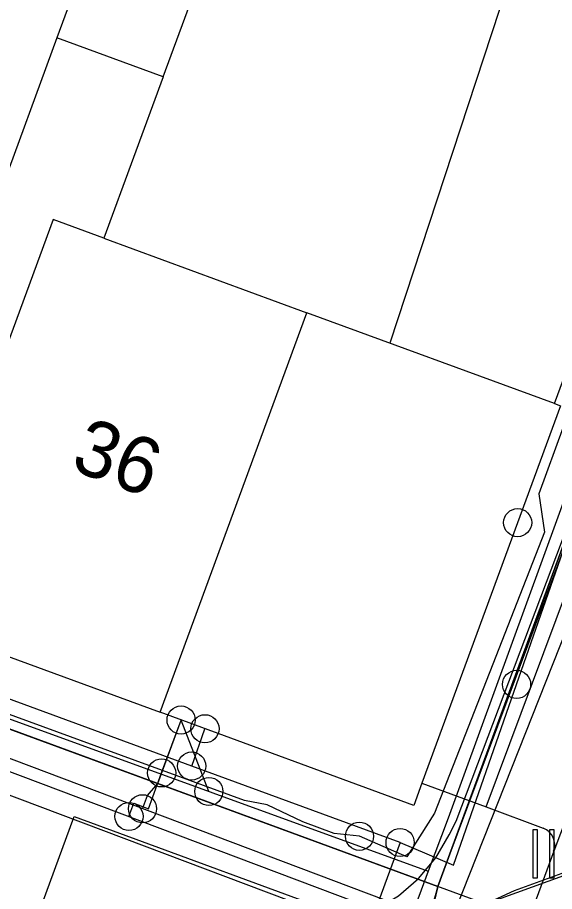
# Model space of a CAD drawing. Extents: x 192672 to 192910, y 446344 to 446512.
# Drawn here: x 192731.6 to 192741.13, y 446406.75 to 446422.27 of the extents above; entities that cross this region are included whole.
import ezdxf

# ---------------------------------------------------------------- set-up
doc = ezdxf.new("R2010")
doc.units = 0
for name, color, linetype in [('B-OI-KL-()_PUNTVANLEVERING_WATER-S', 7, 'Continuous'), ('B-OI-KL-BUISLEIDING_OLIEGASCHEMICALIEN_GASLAGEDRUK-G', 7, 'Continuous'), ('B-OI-KL-DATA-G', 7, 'Continuous'), ('B-OI-KL-DATA_GTWP-S', 7, 'Continuous'), ('B-OI-KL-DATA_HANDHOLE-S', 7, 'Continuous'), ('B-OI-KL-DATA_KABELBED-G', 7, 'Continuous'), ('B-OI-KL-DATA_MOF-S', 7, 'Continuous'), ('B-OI-KL-ET_LS-G', 7, 'Continuous'), ('B-OI-KL-ET_LS_DELIVERYPOINT-S', 7, 'Continuous'), ('B-OI-KL-ET_LS_MOF-S', 7, 'Continuous'), ('B-OI-KL-ET_MS-G', 7, 'Continuous'), ('B-OI-KL-ET_MS_MANTELBUIS-G', 7, 'Continuous'), ('B-OI-KL-GAS_LD_AFTAKZADEL-S', 7, 'Continuous'), ('B-OI-KL-GAS_LD_DELIVERYPOINT-S', 7, 'Continuous'), ('B-OI-KL-WATER-G', 7, 'Continuous'), ('Default', 7, 'Continuous'), ('huisnummerreeks BGT', 7, 'Continuous'), ('kant open verharding', 7, 'Continuous'), ('kant verharding', 7, 'Continuous'), ('kolk', 7, 'Continuous'), ('pand op maaiveld vlak', 7, 'Continuous'), ('verkeerseiland - berm', 7, 'Continuous')]:
    doc.layers.add(name, color=color, linetype=linetype)

# ---------------------------------------------------------------- blocks, each defined once
blk = doc.blocks.new('B-OI-KL-GAS_LD_AFTAKZADEL-S')
at = {"layer": 'Default'}
blk.add_circle((0, 0), 0.25, dxfattribs=at)
blk = doc.blocks.new('B-OI-KL-GAS_LD_DELIVERYPOINT-S')
at = {"layer": 'Default'}
blk.add_circle((0, 0), 0.25, dxfattribs=at)
blk = doc.blocks.new('B-OI-KL-ET_LS_DELIVERYPOINT-S')
at = {"layer": 'Default'}
blk.add_circle((0, 0), 0.25, dxfattribs=at)
blk = doc.blocks.new('B-OI-KL-ET_LS_MOF-S')
at = {"layer": 'Default'}
blk.add_circle((0, 0), 0.25, dxfattribs=at)
blk = doc.blocks.new('B-OI-KL-DATA_HANDHOLE-S')
at = {"layer": 'Default'}
blk.add_circle((0, 0), 0.25, dxfattribs=at)
blk = doc.blocks.new('B-OI-KL-()_PUNTVANLEVERING_WATER-S')
at = {"layer": 'Default'}
blk.add_circle((0, 0), 0.25, dxfattribs=at)
blk = doc.blocks.new('B-OI-KL-DATA_GTWP-S')
at = {"layer": 'Default'}
blk.add_circle((0, 0), 0.25, dxfattribs=at)
blk = doc.blocks.new('B-OI-KL-DATA_MOF-S')
at = {"layer": 'Default'}
blk.add_circle((0, 0), 0.25, dxfattribs=at)

msp = doc.modelspace()

# ---------------------------------------------------------------- linework, layer by layer
at = {"layer": 'B-OI-KL-BUISLEIDING_OLIEGASCHEMICALIEN_GASLAGEDRUK-G'}
for points in [[(192739.245, 446406.116), (192738.416, 446406.482), (192717.09, 446414.534), (192687.866, 446425.386), (192686.502, 446425.892), (192685.933, 446426.1), (192675.743, 446429.821)], [(192742.217, 446413.618), (192739.245, 446406.116)], [(192733.815, 446408.219), (192733.903, 446408.453), (192734.086, 446408.668), (192734.5, 446409.795)]]:
    msp.add_lwpolyline(points, dxfattribs=at)
at = {"layer": 'B-OI-KL-DATA-G'}
for points in [[(192768.74, 446486.807), (192749.794, 446435.599), (192742.072, 446415.039), (192739.06, 446406.841), (192720.2, 446413.77), (192719.012, 446414.118), (192696.077, 446422.823), (192683.193, 446427.673), (192678.122, 446429.261), (192675.743, 446430.156)], [(192768.74, 446486.807), (192749.794, 446435.599), (192742.072, 446415.039), (192739.06, 446406.841), (192738.917, 446406.249), (192738.75, 446405.758), (192738.438, 446405.088), (192738.002, 446404.406), (192737.543, 446403.858), (192737.067, 446403.408), (192736.56, 446403.025), (192736.06, 446402.723), (192733.684, 446396.245), (192734.518, 446394.712), (192730.316, 446383.423), (192727.316, 446375.697), (192722.899, 446364.033), (192722.458, 446362.715), (192718.077, 446351.086), (192716.68, 446347.404), (192715.968, 446345.556)], [(192768.74, 446486.807), (192749.794, 446435.599), (192742.072, 446415.039), (192739.06, 446406.841), (192738.917, 446406.249), (192738.75, 446405.758), (192738.438, 446405.088), (192738.002, 446404.406), (192737.543, 446403.858), (192737.067, 446403.408), (192736.56, 446403.025), (192736.06, 446402.723), (192733.684, 446396.245), (192734.518, 446394.712), (192730.316, 446383.423), (192727.316, 446375.697), (192722.899, 446364.033), (192722.458, 446362.715), (192718.077, 446351.086), (192716.68, 446347.404), (192715.968, 446345.556)], [(192768.74, 446486.807), (192749.794, 446435.599), (192742.072, 446415.039), (192739.06, 446406.841), (192738.917, 446406.249), (192738.75, 446405.758), (192738.438, 446405.088), (192738.002, 446404.406), (192737.543, 446403.858), (192737.067, 446403.408), (192736.56, 446403.025), (192736.06, 446402.723), (192733.684, 446396.245), (192734.518, 446394.712), (192730.316, 446383.423), (192727.316, 446375.697), (192722.899, 446364.033), (192722.458, 446362.715), (192718.077, 446351.086), (192716.68, 446347.404), (192715.968, 446345.556)], [(192768.74, 446486.807), (192749.794, 446435.599), (192742.072, 446415.039), (192739.06, 446406.841), (192738.917, 446406.249), (192738.75, 446405.758), (192738.438, 446405.088), (192738.002, 446404.406), (192737.543, 446403.858), (192737.067, 446403.408), (192736.56, 446403.025), (192736.06, 446402.723), (192733.684, 446396.245), (192734.518, 446394.712), (192730.316, 446383.423), (192727.316, 446375.697), (192722.899, 446364.033), (192722.458, 446362.715), (192718.077, 446351.086), (192716.68, 446347.404), (192715.968, 446345.556)], [(192768.74, 446486.807), (192749.794, 446435.599), (192742.072, 446415.039), (192739.06, 446406.841), (192738.917, 446406.249), (192738.75, 446405.758), (192738.438, 446405.088), (192738.002, 446404.406), (192737.543, 446403.858), (192737.067, 446403.408), (192736.56, 446403.025), (192736.06, 446402.723), (192733.684, 446396.245), (192734.518, 446394.712), (192730.316, 446383.423), (192727.316, 446375.697), (192722.899, 446364.033), (192722.458, 446362.715), (192718.077, 446351.086), (192716.68, 446347.404), (192715.968, 446345.556)], [(192768.74, 446486.807), (192749.794, 446435.599), (192742.072, 446415.039), (192739.06, 446406.841), (192738.917, 446406.249), (192738.75, 446405.758), (192738.438, 446405.088), (192738.002, 446404.406), (192737.543, 446403.858), (192737.067, 446403.408), (192736.56, 446403.025), (192736.06, 446402.723), (192733.684, 446396.245), (192734.518, 446394.712), (192730.316, 446383.423), (192727.316, 446375.697), (192722.899, 446364.033), (192722.458, 446362.715), (192718.077, 446351.086), (192716.68, 446347.404), (192715.968, 446345.556)], [(192768.74, 446486.807), (192749.794, 446435.599), (192742.072, 446415.039), (192739.06, 446406.841), (192738.917, 446406.249), (192738.75, 446405.758), (192738.438, 446405.088), (192738.002, 446404.406), (192737.543, 446403.858), (192737.067, 446403.408), (192736.56, 446403.025), (192736.06, 446402.723), (192733.684, 446396.245), (192734.518, 446394.712), (192730.316, 446383.423), (192727.316, 446375.697), (192722.899, 446364.033), (192722.458, 446362.715), (192718.077, 446351.086), (192716.68, 446347.404), (192715.968, 446345.556)], [(192768.74, 446486.807), (192749.794, 446435.599), (192742.072, 446415.039), (192739.06, 446406.841), (192738.917, 446406.249), (192738.75, 446405.758), (192738.438, 446405.088), (192738.002, 446404.406), (192737.543, 446403.858), (192737.067, 446403.408), (192736.56, 446403.025), (192736.06, 446402.723), (192733.684, 446396.245), (192734.518, 446394.712), (192730.316, 446383.423), (192727.316, 446375.697), (192722.899, 446364.033), (192722.458, 446362.715), (192718.077, 446351.086), (192716.68, 446347.404), (192715.968, 446345.556)], [(192768.74, 446486.807), (192749.794, 446435.599), (192742.072, 446415.039), (192739.06, 446406.841), (192738.917, 446406.249), (192738.75, 446405.758), (192738.438, 446405.088), (192738.002, 446404.406), (192737.543, 446403.858), (192737.067, 446403.408), (192736.56, 446403.025), (192736.06, 446402.723), (192733.684, 446396.245), (192734.518, 446394.712), (192730.316, 446383.423), (192727.316, 446375.697), (192722.899, 446364.033), (192722.458, 446362.715), (192718.077, 446351.086), (192716.68, 446347.404), (192715.968, 446345.556)], [(192768.74, 446486.807), (192749.794, 446435.599), (192742.072, 446415.039), (192739.06, 446406.841), (192738.917, 446406.249), (192738.75, 446405.758), (192738.438, 446405.088), (192738.002, 446404.406), (192737.543, 446403.858), (192737.067, 446403.408), (192736.56, 446403.025), (192736.06, 446402.723), (192733.684, 446396.245), (192734.518, 446394.712), (192730.316, 446383.423), (192727.316, 446375.697), (192722.899, 446364.033), (192722.458, 446362.715), (192718.077, 446351.086), (192716.68, 446347.404), (192715.968, 446345.556)], [(192768.74, 446486.807), (192749.794, 446435.599), (192742.072, 446415.039), (192739.06, 446406.841), (192738.917, 446406.249), (192738.75, 446405.758), (192738.438, 446405.088), (192738.002, 446404.406), (192737.543, 446403.858), (192737.067, 446403.408), (192736.56, 446403.025), (192736.06, 446402.723), (192733.684, 446396.245), (192734.518, 446394.712), (192730.316, 446383.423), (192727.316, 446375.697), (192722.899, 446364.033), (192722.458, 446362.715), (192718.077, 446351.086), (192716.68, 446347.404), (192715.968, 446345.556)], [(192768.74, 446486.807), (192749.794, 446435.599), (192742.072, 446415.039), (192739.06, 446406.841), (192738.917, 446406.249), (192738.75, 446405.758), (192738.438, 446405.088), (192738.002, 446404.406), (192737.543, 446403.858), (192737.067, 446403.408), (192736.56, 446403.025), (192736.06, 446402.723), (192733.684, 446396.245), (192734.518, 446394.712), (192730.316, 446383.423), (192727.316, 446375.697), (192722.899, 446364.033), (192722.458, 446362.715), (192718.077, 446351.086), (192716.68, 446347.404), (192715.968, 446345.556)], [(192768.74, 446486.807), (192749.794, 446435.599), (192742.072, 446415.039), (192739.06, 446406.841), (192738.917, 446406.249), (192738.75, 446405.758), (192738.438, 446405.088), (192738.002, 446404.406), (192737.543, 446403.858), (192737.067, 446403.408), (192736.56, 446403.025), (192736.06, 446402.723), (192733.684, 446396.245), (192734.518, 446394.712), (192730.316, 446383.423), (192727.316, 446375.697), (192722.899, 446364.033), (192722.458, 446362.715), (192718.077, 446351.086), (192716.68, 446347.404), (192715.968, 446345.556)], [(192768.74, 446486.807), (192749.794, 446435.599), (192742.072, 446415.039), (192739.06, 446406.841), (192738.917, 446406.249), (192738.75, 446405.758), (192738.438, 446405.088), (192738.002, 446404.406), (192737.543, 446403.858), (192737.067, 446403.408), (192736.56, 446403.025), (192736.06, 446402.723), (192733.684, 446396.245), (192734.518, 446394.712), (192730.316, 446383.423), (192727.316, 446375.697), (192722.899, 446364.033), (192722.458, 446362.715), (192718.077, 446351.086), (192716.68, 446347.404), (192715.968, 446345.556)], [(192768.74, 446486.807), (192749.794, 446435.599), (192742.072, 446415.039), (192739.06, 446406.841), (192738.917, 446406.249), (192738.75, 446405.758), (192738.438, 446405.088), (192738.002, 446404.406), (192737.543, 446403.858), (192737.067, 446403.408), (192736.56, 446403.025), (192736.06, 446402.723), (192733.684, 446396.245), (192734.518, 446394.712), (192730.316, 446383.423), (192727.316, 446375.697), (192722.899, 446364.033), (192722.458, 446362.715), (192718.077, 446351.086), (192716.68, 446347.404), (192715.968, 446345.556)], [(192733.785, 446392.743), (192734.518, 446394.712), (192733.684, 446396.245), (192736.06, 446402.723), (192736.56, 446403.025), (192737.067, 446403.408), (192737.543, 446403.858), (192738.002, 446404.406), (192738.438, 446405.088), (192738.75, 446405.758), (192738.917, 446406.249), (192739.06, 446406.841), (192742.072, 446415.039), (192749.794, 446435.599), (192768.74, 446486.807)], [(192675.743, 446430.36), (192720.2, 446413.771), (192739.906, 446406.53), (192752.421, 446411.058), (192770.152, 446404.44), (192773.577, 446403.064), (192825.629, 446383.71), (192826.856, 446388.539), (192834.171, 446407.983), (192839.017, 446421.742), (192838.042, 446426.7), (192842.865, 446440.095), (192846.683, 446450.008), (192848.26, 446453.903), (192848.365, 446454.374), (192848.254, 446454.945), (192844.011, 446462.681), (192860.643, 446470.952)], [(192745.236, 446436.264), (192745.276, 446436.371), (192749.491, 446434.791), (192742.072, 446415.039), (192739.06, 446406.841), (192720.2, 446413.77), (192719.012, 446414.118), (192696.077, 446422.823), (192683.193, 446427.673), (192678.122, 446429.261), (192675.743, 446430.156)], [(192745.236, 446436.264), (192745.276, 446436.371), (192749.491, 446434.791), (192742.072, 446415.039), (192739.06, 446406.841), (192725.038, 446411.993)], [(192737.667, 446407.73), (192737.22, 446407.782), (192736.663, 446407.985), (192736.03, 446408.286), (192735.626, 446408.365), (192729.863, 446410.472), (192728.465, 446411.08), (192721.146, 446413.773), (192716.247, 446415.615), (192710.715, 446417.628), (192706.774, 446419.101), (192701.477, 446421.077), (192698.04, 446422.325), (192693.262, 446424.115), (192691.867, 446424.65), (192684.239, 446427.468), (192680.591, 446428.834), (192677.798, 446429.859), (192675.743, 446430.624)], [(192675.743, 446430.156), (192678.122, 446429.261), (192683.193, 446427.673), (192696.077, 446422.823), (192719.012, 446414.118), (192720.2, 446413.77), (192739.06, 446406.841), (192738.917, 446406.249), (192738.75, 446405.758), (192738.438, 446405.088), (192738.002, 446404.406), (192737.543, 446403.858), (192737.067, 446403.408), (192736.56, 446403.025), (192736.06, 446402.723), (192733.684, 446396.245), (192734.518, 446394.712), (192730.316, 446383.423), (192727.316, 446375.697), (192722.899, 446364.033), (192722.458, 446362.715), (192718.077, 446351.086), (192716.68, 446347.404), (192715.968, 446345.556)], [(192675.743, 446430.156), (192678.122, 446429.261), (192683.193, 446427.673), (192696.077, 446422.823), (192719.012, 446414.118), (192720.2, 446413.77), (192739.06, 446406.841), (192738.917, 446406.249), (192738.75, 446405.758), (192738.438, 446405.088), (192738.002, 446404.406), (192737.543, 446403.858), (192737.067, 446403.408), (192736.56, 446403.025), (192736.06, 446402.723), (192733.684, 446396.245), (192734.518, 446394.712), (192730.316, 446383.423), (192727.316, 446375.697), (192722.899, 446364.033), (192722.458, 446362.715), (192718.077, 446351.086), (192716.68, 446347.404), (192715.968, 446345.556)], [(192675.743, 446430.156), (192678.122, 446429.261), (192683.193, 446427.673), (192696.077, 446422.823), (192719.012, 446414.118), (192720.2, 446413.77), (192739.06, 446406.841), (192738.917, 446406.249), (192738.75, 446405.758), (192738.438, 446405.088), (192738.002, 446404.406), (192737.543, 446403.858), (192737.067, 446403.408), (192736.56, 446403.025), (192736.06, 446402.723), (192733.684, 446396.245), (192734.518, 446394.712), (192730.316, 446383.423), (192727.316, 446375.697), (192722.899, 446364.033), (192722.458, 446362.715), (192718.077, 446351.086), (192716.68, 446347.404), (192715.968, 446345.556)], [(192675.743, 446430.156), (192678.122, 446429.261), (192683.193, 446427.673), (192696.077, 446422.823), (192719.012, 446414.118), (192720.2, 446413.77), (192739.06, 446406.841), (192738.917, 446406.249), (192738.75, 446405.758), (192738.438, 446405.088), (192738.002, 446404.406), (192737.543, 446403.858), (192737.067, 446403.408), (192736.56, 446403.025), (192736.06, 446402.723), (192733.684, 446396.245), (192734.518, 446394.712), (192730.316, 446383.423), (192727.316, 446375.697), (192722.899, 446364.033), (192722.458, 446362.715), (192718.077, 446351.086), (192716.68, 446347.404), (192715.968, 446345.556)], [(192675.743, 446430.156), (192678.122, 446429.261), (192683.193, 446427.673), (192696.077, 446422.823), (192719.012, 446414.118), (192720.2, 446413.77), (192739.06, 446406.841), (192738.917, 446406.249), (192738.75, 446405.758), (192738.438, 446405.088), (192738.002, 446404.406), (192737.543, 446403.858), (192737.067, 446403.408), (192736.56, 446403.025), (192736.06, 446402.723), (192733.684, 446396.245), (192734.518, 446394.712), (192730.316, 446383.423), (192727.316, 446375.697), (192722.899, 446364.033), (192722.458, 446362.715), (192718.077, 446351.086), (192716.68, 446347.404), (192715.968, 446345.556)], [(192675.743, 446430.156), (192678.122, 446429.261), (192683.193, 446427.673), (192696.077, 446422.823), (192719.012, 446414.118), (192720.2, 446413.77), (192739.06, 446406.841), (192738.917, 446406.249), (192738.75, 446405.758), (192738.438, 446405.088), (192738.002, 446404.406), (192737.543, 446403.858), (192737.067, 446403.408), (192736.56, 446403.025), (192736.06, 446402.723), (192733.684, 446396.245), (192734.518, 446394.712), (192730.316, 446383.423), (192727.316, 446375.697), (192722.899, 446364.033), (192722.458, 446362.715), (192718.077, 446351.086), (192716.68, 446347.404), (192715.968, 446345.556)], [(192745.619, 446424.697), (192745.237, 446423.754), (192744.239, 446422.5), (192741.607, 446415.471), (192741.284, 446414.993), (192740.849, 446413.811), (192740.953, 446413.129), (192738.997, 446408.143), (192738.51, 446407.367), (192737.667, 446407.73)], [(192753.019, 446415.296), (192753.389, 446416.428), (192755.111, 446420.888), (192753.608, 446421.506), (192747.333, 446423.998), (192746.061, 446424.511), (192745.619, 446424.697), (192745.237, 446423.754), (192744.239, 446422.5), (192741.607, 446415.471), (192741.284, 446414.993), (192740.849, 446413.811), (192740.953, 446413.129), (192738.997, 446408.143), (192738.51, 446407.367), (192737.667, 446407.73)], [(192715.968, 446345.556), (192716.68, 446347.404), (192718.077, 446351.086), (192722.458, 446362.715), (192722.899, 446364.033), (192727.316, 446375.697), (192730.316, 446383.423), (192734.518, 446394.712), (192733.684, 446396.245), (192736.06, 446402.723), (192736.56, 446403.025), (192737.067, 446403.408), (192737.543, 446403.858), (192738.002, 446404.406), (192738.438, 446405.088), (192738.75, 446405.758), (192738.917, 446406.249), (192739.06, 446406.841), (192720.2, 446413.77), (192719.012, 446414.118), (192698.154, 446422.035)], [(192715.968, 446345.556), (192716.68, 446347.404), (192718.077, 446351.086), (192722.458, 446362.715), (192722.899, 446364.033), (192727.316, 446375.697), (192730.316, 446383.423), (192734.518, 446394.712), (192733.684, 446396.245), (192736.06, 446402.723), (192736.56, 446403.025), (192737.067, 446403.408), (192737.543, 446403.858), (192738.002, 446404.406), (192738.438, 446405.088), (192738.75, 446405.758), (192738.917, 446406.249), (192739.06, 446406.841), (192720.2, 446413.77), (192719.012, 446414.118), (192703.056, 446420.174)], [(192715.968, 446345.556), (192716.68, 446347.404), (192718.077, 446351.086), (192722.458, 446362.715), (192722.899, 446364.033), (192727.316, 446375.697), (192730.316, 446383.423), (192734.518, 446394.712), (192733.684, 446396.245), (192736.06, 446402.723), (192736.56, 446403.025), (192737.067, 446403.408), (192737.543, 446403.858), (192738.002, 446404.406), (192738.438, 446405.088), (192738.75, 446405.758), (192738.917, 446406.249), (192739.06, 446406.841), (192720.2, 446413.77), (192719.012, 446414.118), (192707.704, 446418.41)], [(192737.667, 446407.73), (192737.22, 446407.782), (192736.663, 446407.985), (192736.03, 446408.286), (192735.626, 446408.365), (192729.863, 446410.472)]]:
    msp.add_lwpolyline(points, dxfattribs=at)
at = {"layer": 'B-OI-KL-DATA_KABELBED-G'}
for points in [[(192739.06, 446406.841), (192749.491, 446434.791)], [(192738.388, 446407.619), (192734.688, 446408.978), (192724.883, 446412.582), (192723.845, 446412.963), (192720.372, 446414.239), (192719.183, 446414.479), (192716.646, 446415.427), (192714.21, 446416.337), (192707.529, 446418.834), (192703.97, 446420.164), (192697.852, 446422.451), (192697.2, 446422.694), (192695.696, 446423.256), (192692.683, 446424.382), (192687.423, 446426.348), (192680.18, 446429.054), (192675.857, 446430.67), (192675.743, 446430.712)], [(192740.848, 446424.525), (192738.205, 446416.488)], [(192740.456, 446410.428), (192741.713, 446414.036)], [(192739.06, 446406.841), (192725.038, 446411.993)], [(192738.388, 446407.619), (192739.338, 446407.217), (192740.456, 446410.428)], [(192734.688, 446408.978), (192734.924, 446409.639)], [(192738.388, 446407.619), (192737.146, 446404.239), (192733.82, 446395.718)], [(192739.06, 446406.841), (192738.75, 446405.758), (192738.438, 446405.088), (192738.002, 446404.406), (192737.067, 446403.408), (192736.06, 446402.723)]]:
    msp.add_lwpolyline(points, dxfattribs=at)
at = {"layer": 'B-OI-KL-ET_LS-G'}
for points in [[(192737.952, 446406.43), (192738.358, 446406.675), (192738.717, 446406.983), (192739.022, 446407.347), (192739.262, 446407.755), (192739.381, 446408.001), (192760.347, 446463.479), (192768.676, 446485.881)], [(192675.743, 446430.115), (192687.837, 446425.34), (192737.952, 446406.43)], [(192751.683, 446410.693), (192751.552, 446410.731), (192751.472, 446410.738), (192751.395, 446410.716), (192751.332, 446410.668), (192751.29, 446410.599), (192748.269, 446402.545), (192740.519, 446405.455), (192737.866, 446406.039), (192687.696, 446424.966), (192675.743, 446429.685)], [(192734.155, 446408.856), (192734.5, 446409.795)], [(192733.575, 446408.082), (192733.663, 446408.316), (192733.921, 446408.219), (192734.155, 446408.856)]]:
    msp.add_lwpolyline(points, dxfattribs=at)
at = {"layer": 'B-OI-KL-ET_MS-G'}
msp.add_lwpolyline([(192675.743, 446430.392), (192719.08, 446414.198), (192720.2, 446413.771), (192739.907, 446406.53), (192740.419, 446406.767), (192749.859, 446410.199), (192752.421, 446411.058), (192770.152, 446404.44), (192774.571, 446402.692), (192787.766, 446397.768), (192806.764, 446390.772), (192825.096, 446383.91)], dxfattribs=at)
at = {"layer": 'B-OI-KL-ET_MS_MANTELBUIS-G'}
msp.add_lwpolyline([(192740.419, 446406.767), (192749.859, 446410.199)], dxfattribs=at)
at = {"layer": 'B-OI-KL-WATER-G'}
msp.add_line((192675.743, 446430.057), (192738.889, 446407.111), dxfattribs=at)
for points in [[(192741.468, 446414.159), (192739.24, 446408.053), (192738.889, 446407.111)], [(192734.993, 446408.526), (192734.5, 446409.795)], [(192738.889, 446407.111), (192738.576, 446406.273)]]:
    msp.add_lwpolyline(points, dxfattribs=at)
at = {"layer": 'kant open verharding'}
for p, q in [((192741.127, 446415.414), (192744.037, 446423.324)), ((192738.776, 446408.675), (192739.919, 446408.255))]:
    msp.add_line(p, q, dxfattribs=at)
at = {"layer": 'kant verharding'}
for p, q in [((192751.119, 446434.16), (192741.115, 446407.463)), ((192739.919, 446408.255), (192740.927, 446407.876)), ((192741.115, 446407.463), (192740.44, 446405.64))]:
    msp.add_line(p, q, dxfattribs=at)
msp.add_lwpolyline([(192739.919, 446408.255), (192749.62, 446434.241), (192750.477, 446433.889)], dxfattribs=at)
msp.add_arc((192740.812, 446407.575), 0.322, 339.7634, 69.1872, dxfattribs=at)
at = {"layer": 'kolk'}
for points in [[(192740.828, 446407.418), (192740.828, 446407.843), (192740.743, 446407.843), (192740.743, 446407.418), (192740.743, 446406.993), (192740.828, 446406.993)], [(192741.126, 446407.418), (192741.126, 446407.843), (192741.041, 446407.843), (192741.041, 446407.418), (192741.041, 446406.993), (192741.126, 446406.993)]]:
    msp.add_lwpolyline(points, close=True, dxfattribs=at)
at = {"layer": 'pand op maaiveld vlak'}
for p, q in [((192734.182, 446421.216), (192732.296, 446421.908)), ((192734.182, 446421.216), (192733.13, 446418.353)), ((192733.13, 446418.353), (192736.734, 446417.029)), ((192734.126, 446409.932), (192736.734, 446417.029)), ((192741.127, 446415.414), (192736.734, 446417.029)), ((192729.622, 446411.587), (192734.126, 446409.932))]:
    msp.add_line(p, q, dxfattribs=at)
for points in [[(192734.182, 446421.216), (192735.234, 446424.078), (192734.332, 446424.409), (192733.348, 446424.771), (192732.296, 446421.908)], [(192732.296, 446421.908), (192731.243, 446419.044), (192727.725, 446420.338)], [(192733.13, 446418.353), (192732.229, 446418.684), (192729.622, 446411.587)], [(192741.127, 446415.414), (192741.237, 446415.373), (192738.776, 446408.675)], [(192738.776, 446408.675), (192738.63, 446408.277), (192734.126, 446409.932)]]:
    msp.add_lwpolyline(points, dxfattribs=at)
at = {"layer": 'verkeerseiland - berm'}
msp.add_lwpolyline([(192731.902, 446406.177), (192732.604, 446408.083), (192737.948, 446406.115), (192737.245, 446404.209)], dxfattribs=at)

# ---------------------------------------------------------------- block references
at = {"layer": 'B-OI-KL-()_PUNTVANLEVERING_WATER-S'}
msp.add_blockref('B-OI-KL-()_PUNTVANLEVERING_WATER-S', (192734.993, 446408.526), dxfattribs=at)
at = {"layer": 'B-OI-KL-DATA_GTWP-S'}
for p in [(192740.456, 446410.428), (192740.456, 446410.428), (192734.924, 446409.639), (192734.688, 446408.978), (192738.388, 446407.619), (192738.388, 446407.619), (192738.388, 446407.619)]:
    msp.add_blockref('B-OI-KL-DATA_GTWP-S', p, dxfattribs=at)
at = {"layer": 'B-OI-KL-DATA_HANDHOLE-S'}
msp.add_blockref('B-OI-KL-DATA_HANDHOLE-S', (192737.667, 446407.73), dxfattribs=at)
at = {"layer": 'B-OI-KL-DATA_MOF-S'}
msp.add_blockref('B-OI-KL-DATA_MOF-S', (192734.688, 446408.978), dxfattribs=at)
at = {"layer": 'B-OI-KL-ET_LS_DELIVERYPOINT-S'}
msp.add_blockref('B-OI-KL-ET_LS_DELIVERYPOINT-S', (192740.475, 446413.3), dxfattribs=at)
at = {"layer": 'B-OI-KL-ET_LS_MOF-S'}
for p in [(192734.5, 446409.795), (192734.155, 446408.856), (192733.575, 446408.082)]:
    msp.add_blockref('B-OI-KL-ET_LS_MOF-S', p, dxfattribs=at)
at = {"layer": 'B-OI-KL-GAS_LD_AFTAKZADEL-S'}
msp.add_blockref('B-OI-KL-GAS_LD_AFTAKZADEL-S', (192733.815, 446408.219), dxfattribs=at)
at = {"layer": 'B-OI-KL-GAS_LD_DELIVERYPOINT-S'}
msp.add_blockref('B-OI-KL-GAS_LD_DELIVERYPOINT-S', (192734.5, 446409.795), dxfattribs=at)

# ---------------------------------------------------------------- texts
at = {"layer": 'huisnummerreeks BGT'}
msp.add_text('36', height=1, rotation=339.9, dxfattribs=at).set_placement((192732.51, 446414.253))

doc.saveas('drawing.dxf')
